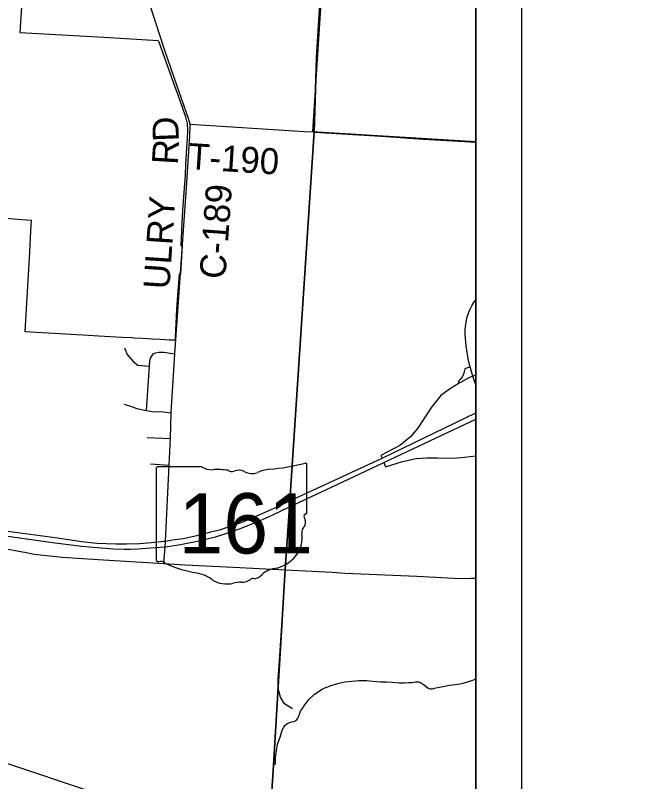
# Model space of a CAD drawing. Extents: x 0 to 34, y 0 to 22.
# Drawn here: x 7.893 to 9.25, y 17.262 to 18.938 of the extents above; entities that cross this region are included whole.
import ezdxf

# ---------------------------------------------------------------- set-up
doc = ezdxf.new("R2010")
doc.units = 0
for name, color, linetype in [('Default', 7, 'Continuous'), ('GM_X_City_Street', 7, 'Continuous'), ('GM_X_Corporation', 7, 'Continuous'), ('GM_X_County_Road', 7, 'Continuous'), ('GM_X_County_Road_Text', 7, 'Continuous'), ('GM_X_Interchange_Ramps', 7, 'Continuous'), ('GM_X_State_Location', 7, 'Continuous'), ('GM_X_State_Route', 7, 'Continuous'), ('GM_X_State_Shield', 7, 'Continuous'), ('GM_X_Township_Road_Text', 7, 'Continuous'), ('SH_Data', 7, 'Continuous'), ('SH_Text', 7, 'Continuous')]:
    doc.layers.add(name, color=color, linetype=linetype)

msp = doc.modelspace()

# ---------------------------------------------------------------- linework, layer by layer
at = {"layer": 'Default'}
msp.add_lwpolyline([(8.9, 18.6616), (8.9, 19.1966), (8.5782, 19.2201), (8.5779, 19.2144), (8.5637, 18.9993), (8.5431, 18.6841)], close=True, dxfattribs=at)
at = {"layer": 'GM_X_City_Street'}
for p, q in [((8.1814, 18.0145), (8.2325, 18.0125)), ((8.1883, 17.9571), (8.2294, 17.9538))]:
    msp.add_line(p, q, dxfattribs=at)
for points in [[(8.2751, 18.6998), (8.5255, 18.6841), (8.5445, 18.6828)], [(8.5445, 18.6828), (8.5465, 18.6827), (8.7045, 18.6729), (8.7852, 18.6674), (8.8501, 18.6637), (8.9, 18.6605)], [(8.877, 18.2485), (8.8771, 18.2517), (8.8781, 18.2619), (8.8801, 18.2712), (8.8817, 18.2784), (8.8845, 18.2866), (8.8868, 18.2925), (8.8914, 18.3025), (8.8967, 18.3112), (8.9, 18.3159)], [(8.888, 18.1693), (8.8845, 18.1822), (8.8791, 18.2154), (8.8767, 18.24), (8.877, 18.2485)], [(8.1315, 18.2107), (8.1376, 18.1963), (8.1512, 18.18), (8.1608, 18.1731), (8.1866, 18.1704)], [(8.1798, 18.0737), (8.1866, 18.1704), (8.1874, 18.1819), (8.1888, 18.188), (8.1943, 18.1975), (8.2, 18.1998), (8.2065, 18.201), (8.2179, 18.201), (8.2415, 18.1975)], [(8.9, 18.1302), (8.8986, 18.1338), (8.8937, 18.1485), (8.888, 18.1693)], [(8.131, 18.0878), (8.1467, 18.0824), (8.1588, 18.0779), (8.1798, 18.0737), (8.1924, 18.0714), (8.216, 18.0706), (8.2337, 18.0685)], [(8.4992, 17.4211), (8.4818, 17.4321), (8.4727, 17.4466), (8.4684, 17.463), (8.4678, 17.4868), (8.47, 17.515), (8.4836, 17.7255)], [(8.4576, 17.2978), (8.4617, 17.3017), (8.4622, 17.3159), (8.4636, 17.3231), (8.4642, 17.3304), (8.4659, 17.3392), (8.4675, 17.3465), (8.4698, 17.3537), (8.4728, 17.3616), (8.4754, 17.3695), (8.4777, 17.3764), (8.4803, 17.381), (8.4826, 17.3849), (8.4876, 17.3892), (8.4918, 17.3909), (8.4974, 17.3928), (8.5027, 17.3935), (8.5073, 17.3958), (8.5102, 17.3991), (8.5125, 17.404), (8.5145, 17.4099), (8.5171, 17.4162), (8.5211, 17.4218), (8.5244, 17.4274), (8.5283, 17.4326), (8.5313, 17.4369), (8.5359, 17.4422), (8.5428, 17.4491), (8.5477, 17.453), (8.553, 17.4566), (8.5586, 17.4606), (8.5645, 17.4639), (8.5701, 17.4668), (8.5767, 17.4694), (8.5829, 17.4721), (8.5908, 17.4744), (8.5987, 17.4767), (8.6069, 17.479), (8.6135, 17.48), (8.6217, 17.4813), (8.6293, 17.4819), (8.6375, 17.4823), (8.6444, 17.4829), (8.6526, 17.4829), (8.6618, 17.4829), (8.674, 17.4819), (8.6917, 17.4806), (8.7052, 17.48), (8.7171, 17.4793), (8.7325, 17.4783), (8.7444, 17.4783), (8.7529, 17.4787), (8.7611, 17.479), (8.768, 17.48), (8.7759, 17.48), (8.7812, 17.4777), (8.7855, 17.4744), (8.7917, 17.4698), (8.7957, 17.4665), (8.8006, 17.4652), (8.8055, 17.4652), (8.8101, 17.4665), (8.8167, 17.4678), (8.8279, 17.4701), (8.8427, 17.4727), (8.8555, 17.4747), (8.8696, 17.477), (8.8821, 17.4803), (8.894, 17.4842), (8.9, 17.4866)], [(8.3913, 16.1519), (8.3994, 16.2974), (8.4048, 16.4377), (8.4153, 16.557), (8.4248, 16.7338), (8.4513, 17.1946), (8.4576, 17.2978)]]:
    msp.add_lwpolyline(points, dxfattribs=at)
at = {"layer": 'GM_X_Corporation'}
for points in [[(8.9, 16.0691), (8.9, 20.2026)], [(7.908, 18.98), (7.9029, 18.9004), (8.0863, 18.8898), (8.2055, 18.8828), (8.2067, 18.8797), (8.2161, 18.8533), (8.2256, 18.827), (8.2391, 18.7892), (8.2481, 18.7641), (8.2578, 18.737), (8.2655, 18.7156), (8.2688, 18.7014), (8.2686, 18.6995), (8.2689, 18.6976), (8.269, 18.6957), (8.2693, 18.6915), (8.2693, 18.6872), (8.2692, 18.683), (8.2651, 18.6117), (8.2644, 18.588), (8.2586, 18.5124), (8.2585, 18.5083), (8.2581, 18.4995), (8.2547, 18.4339), (8.258, 18.4342), (8.2543, 18.3718), (8.251, 18.3719), (8.247, 18.3157), (8.2457, 18.2945), (8.2426, 18.2333), (8.2421, 18.227), (8.239, 18.2272), (8.2294, 18.2277), (8.2198, 18.2283), (8.2099, 18.2289), (8.1933, 18.2298), (8.1707, 18.2311), (8.1522, 18.2321), (8.1482, 18.2324), (8.1266, 18.2336), (8.1009, 18.2351), (8.0745, 18.2366), (8.0531, 18.2378), (7.9773, 18.242), (7.9142, 18.2455), (7.9157, 18.271), (7.9207, 18.3581), (7.9243, 18.4196), (7.927, 18.4669), (7.9283, 18.489), (7.9074, 18.4908), (7.8454, 18.4954)]]:
    msp.add_lwpolyline(points, dxfattribs=at)
at = {"layer": 'GM_X_County_Road'}
msp.add_line((8.8897, 17.7069), (8.9, 17.7072), dxfattribs=at)
for points in [[(8.4511, 17.1951), (8.4574, 17.2984), (8.4834, 17.726), (8.4924, 17.8634), (8.4933, 17.8764), (8.5463, 18.6832), (8.5517, 18.8459), (8.5602, 18.986), (8.5739, 19.2101), (8.5742, 19.2159), (8.5745, 19.2215), (8.6104, 19.8358), (8.636, 20.2294), (8.6772, 20.9), (3.9336, 20.9)], [(8.251, 18.3328), (8.267, 18.5617), (8.2747, 18.6747), (8.2755, 18.6956), (8.2751, 18.6998), (8.2717, 18.7125), (8.2411, 18.7994), (8.2194, 18.8631), (8.1895, 18.9547), (8.1777, 18.9855), (8.1688, 19.0118), (8.1656, 19.03)], [(8.2179, 17.7389), (8.2207, 17.7756), (8.2213, 17.7881), (8.2294, 17.9538), (8.2325, 18.0125), (8.2337, 18.0685), (8.2415, 18.1975), (8.251, 18.3328)], [(7.8134, 17.7824), (7.9086, 17.7645), (7.9137, 17.7636)], [(7.9137, 17.7636), (7.9341, 17.7597), (7.9951, 17.7528), (8.0742, 17.7479), (8.2179, 17.7389), (8.2643, 17.736), (8.3691, 17.7309), (8.4836, 17.7255)], [(8.4836, 17.7255), (8.5863, 17.7202), (8.6147, 17.7181), (8.771, 17.7112), (8.8659, 17.7062), (8.8897, 17.7069)]]:
    msp.add_lwpolyline(points, dxfattribs=at)
msp.add_lwpolyline([(8.9, 16.069), (8.9, 20.9), (8.6772, 20.9), (8.636, 20.2294), (8.6104, 19.8358), (8.5745, 19.2215), (8.5742, 19.2159), (8.5739, 19.2101), (8.5602, 18.986), (8.5517, 18.8459), (8.5463, 18.6832), (8.4933, 17.8764), (8.4924, 17.8634), (8.4834, 17.726), (8.4574, 17.2984), (8.4511, 17.1951), (8.4246, 16.7343), (8.4151, 16.5575), (8.4046, 16.4383), (8.3992, 16.2979), (8.3884, 16.1033), (8.4715, 16.0965), (8.5217, 16.0919)], close=True, dxfattribs=at)
at = {"layer": 'GM_X_Interchange_Ramps'}
msp.add_line((8.9, 18.151), (8.8937, 18.1485), dxfattribs=at)
for points in [[(8.888, 18.1693), (8.8765, 18.1646), (8.8751, 18.1588), (8.873, 18.1525), (8.8701, 18.1472), (8.8659, 18.1415), (8.8617, 18.1374), (8.8638, 18.1332)], [(8.8937, 18.1485), (8.8865, 18.1456), (8.8684, 18.1359), (8.8638, 18.1332), (8.8446, 18.1219), (8.8234, 18.1063), (8.8031, 18.0812), (8.7866, 18.0557), (8.7726, 18.0342), (8.7571, 18.016), (8.7341, 17.9972), (8.6926, 17.9755), (8.6952, 17.9696)], [(8.6992, 17.9601), (8.703, 17.9506), (8.7396, 17.9625), (8.7701, 17.9684), (8.7931, 17.97), (8.8156, 17.97), (8.8167, 17.97)], [(8.8167, 17.97), (8.8419, 17.9697), (8.8594, 17.9702), (8.8754, 17.9715), (8.9, 17.9746)], [(8.9, 17.9774), (8.8996, 17.9787), (8.9, 17.9788)]]:
    msp.add_lwpolyline(points, dxfattribs=at)
at = {"layer": 'GM_X_State_Route'}
msp.add_line((8.6992, 17.9601), (8.9, 18.0546), dxfattribs=at)
for points in [[(8.1359, 17.7821), (8.1644, 17.7828), (8.1907, 17.7852), (8.2179, 17.7876), (8.2213, 17.7881), (8.2368, 17.7905), (8.2602, 17.794), (8.2833, 17.7986), (8.2962, 17.8019), (8.3203, 17.808), (8.3421, 17.8137), (8.3671, 17.8221), (8.3866, 17.8289), (8.4072, 17.8372), (8.4263, 17.8453), (8.4575, 17.8591), (8.4935, 17.8759), (8.6083, 17.9295), (8.6952, 17.9696), (8.9, 18.0688)], [(8.2458, 17.7794), (8.2539, 17.7806), (8.2728, 17.7841), (8.2916, 17.7881), (8.3116, 17.7927), (8.3307, 17.7975), (8.3467, 17.8025), (8.3644, 17.8085), (8.3855, 17.8159), (8.405, 17.8236), (8.4283, 17.8328), (8.4533, 17.8442), (8.4927, 17.8628), (8.609, 17.9179), (8.6992, 17.9601)], [(7.4636, 17.8406), (7.6631, 17.822), (7.683, 17.8201), (7.7367, 17.8153), (7.7883, 17.8104), (7.8604, 17.8008), (7.9802, 17.7843), (8.0383, 17.7773), (8.0716, 17.7738), (8.108, 17.7714), (8.1319, 17.7703), (8.1443, 17.7707)], [(7.86, 17.8122), (7.9799, 17.796), (8.0381, 17.7869), (8.0714, 17.7834), (8.1124, 17.7821), (8.1359, 17.7821)], [(8.1443, 17.7707), (8.1618, 17.7712), (8.1887, 17.7731), (8.2207, 17.7756), (8.2458, 17.7794)]]:
    msp.add_lwpolyline(points, dxfattribs=at)
at = {"layer": 'GM_X_State_Shield'}
for p, q in [((8.301, 17.9505), (8.2045, 17.9505)), ((8.5308, 17.8508), (8.5308, 17.9554)), ((8.2012, 17.947), (8.2012, 17.7469)), ((8.5308, 17.8508), (8.5308, 17.8508))]:
    msp.add_line(p, q, dxfattribs=at)
for centre, major_axis, start_param, end_param in [((8.205, 17.9475), (0.00382, 0), 1.712693, 3.28349), ((8.324, 17.9737), (0.037, 0), 4.042523, 4.731795), ((8.4134, 18.2233), (0.3495, 0), 4.814394, 5.042369), ((8.5272, 17.9559), (0.00367, 0), 6.141152, 7.989035), ((8.3363, 17.8381), (0.133, 0), 1.404758, 1.657858), ((8.3665, 17.9485), (0.0107, 0), 3.836095, 5.185415), ((8.3821, 17.9254), (0.0222, 0), 0.950623, 2.079405), ((8.4108, 17.9571), (0.0267, 0), 4.081561, 5.145723), ((8.458, 17.8894), (0.0703, 0), 1.699011, 2.107814), ((8.5269, 17.8503), (0.00393, 0), 5.05454, 6.418171), ((8.53, 17.8431), (0.00568, 0), 1.883978, 3.671073), ((8.4938, 17.8298), (0.0341, 0), 5.934695, 6.695948), ((8.544, 17.8069), (0.0248, 0), 2.387724, 3.262537), ((8.433, 17.7936), (0.0874, 0), 5.101752, 6.440018), ((8.205, 17.7465), (0.00385, 0), 3.00124, 4.508301), ((8.2056, 17.767), (0.0294, 0), 4.665946, 4.897461), ((8.2116, 17.7354), (0.0106, 0), 0.519207, 1.627899), ((8.3455, 17.9152), (0.2524, 0), 4.195997, 4.488961), ((8.2702, 17.657), (0.079, 0), 0.823519, 1.323587), ((8.4699, 17.6907), (0.0479, 0), 1.647645, 2.488434), ((8.3556, 17.7344), (0.0501, 0), 4.026481, 4.996735), ((8.3846, 17.6652), (0.0412, 0), 1.495662, 1.94098), ((8.3882, 17.7194), (0.0267, 0), 4.691044, 5.507374), ((8.4124, 17.7), (0.00752, 0), 1.147584, 2.315152), ((8.4092, 17.7275), (0.0282, 0), 4.937069, 5.64225)]:
    msp.add_ellipse(centre, major_axis=major_axis, ratio=0.8, start_param=start_param, end_param=end_param, dxfattribs=at)
at = {"layer": 'SH_Data'}
for p, q in [((9, 21), (9, 14)), ((8.9, 20.9), (8.9, 14.1))]:
    msp.add_line(p, q, dxfattribs=at)
at = {"layer": 'SH_Text'}
msp.add_lwpolyline([(9.25, 16.8419), (6.2096, 17.858), (9.25, 16.4941)], close=True, dxfattribs=at)

# ---------------------------------------------------------------- texts
at = {"layer": 'GM_X_County_Road_Text'}
for s, height, rotation, p in [('D', 0.0568, 92.1871, (8.2509, 18.6627)), ('R', 0.0568, 86.6805, (8.2482, 18.6103)), ('C-189', 0.05682, 85.8754, (8.3523, 18.36)), ('ULRY', 0.05682, 86.2196, (8.2298, 18.3377))]:
    msp.add_text(s, height=height, rotation=rotation, dxfattribs=at).set_placement(p)
at = {"layer": 'GM_X_State_Location'}
for s in ['s', 'r']:
    msp.add_text(s, height=0.000189, dxfattribs=at).set_placement((8.3623, 17.8337))
msp.add_text('161', height=0.000189, rotation=0, dxfattribs=at).set_placement((8.2955, 17.8199))
at = {"layer": 'GM_X_State_Shield'}
msp.add_text('161', height=0.13184, dxfattribs=at).set_placement((8.2498, 17.761))
at = {"layer": 'GM_X_Township_Road_Text'}
msp.add_text('T-190', height=0.05682, rotation=356.3536, dxfattribs=at).set_placement((8.27, 18.602))

doc.saveas('drawing.dxf')
